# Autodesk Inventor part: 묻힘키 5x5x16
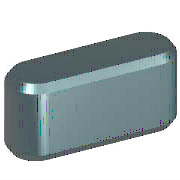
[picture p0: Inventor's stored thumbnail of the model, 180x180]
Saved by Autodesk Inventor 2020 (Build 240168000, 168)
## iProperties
Created: 2012-02
Part Number: 묻힘키 5x5x16
Material: 강철, 연강
Description: 평행 키
Document SubType Name: Modeling
Standard: JIS B 1301
Designer: mdu-01
Standards Organization: JIS
Language: ko-KR
Size Designation: 5x5x16
Categories: <MemberInstance><Categories><Category DisplayName="샤프트 부품" InternalName="7f7aeb1f-a693-4053-b835-cee3144e0d98" Mnemonic="SHFT"><Category DisplayName="키" Interna
Density: 1 g/cm^3
Appearance: 강철(1)
IsCustomPart: 1
Author: mdu-01
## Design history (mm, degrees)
workplane "Work Plane1"
workplane "Work Plane2"
sketch "스케치1"
  geometry: L1 (2.5, 2.5)-(13.5, 2.5); L2 (13.5, -2.5)-(2.5, -2.5); L3 (0, 9.4)-(0, -7.4) reference; L4 (-5, 0)-(30, 0) reference; L5 (16, 0)-(16, 7); A1 r 2.5 centre (2.5, 0) between (2.5, 2.5) and (2.5, -2.5); A2 r 2.5 centre (13.5, 0) between (13.5, -2.5) and (13.5, 2.5)
  constraints: 6 end point, 5 point on circle, 4 tangent, 3 point on line, 2 centre point, 1 horizontal, 1 parallel, 1 perpendicular
  dimensions: "d0" = 2.5 radius of A1 (= 0.5 x PB); "d13" = 2.5 radius of A2 (= 0.5 x PB); "d14" = 16 distance between parallel lines of L5 L3 (= NLG)
extrude "본체1" new body sketch "스케치1" taper "d3" = 0 deg; stored distance "d4" = 10
workplane "Work Plane3"
body "Solid1"
chamfer "모따기1" distance "d8" = 0.4 (= PHH); stored, may be unused: second distance "d9" = 0.4 (= PHH), angle "d15" = 45 deg
other parameters: "d1" = -3 (= -PNT), "d2" = 2 (= PH - PNT), "NLG" = 16 [user parameter; used in 3 equation terms], "PB" = 5 [user parameter; used in 2 equation terms], "PNT" = 3 [user parameter; used in 2 equation terms], "PH" = 5 [user parameter; used in 1 equation term], "PHH" = 0.4 [user parameter; used in 2 equation terms], "d10" = 0, "d16" = 0, "d17" = 0, "d18" = 0, "WDMIN" = 12 [user parameter], "PLB2" = 16 (= NLG) [user parameter], "WDMAX" = 17 [user parameter], "PLB1" = 16 (= NLG) [user parameter], "RR" = 0.16 [user parameter], "PUEB" = 2.3 [user parameter]
